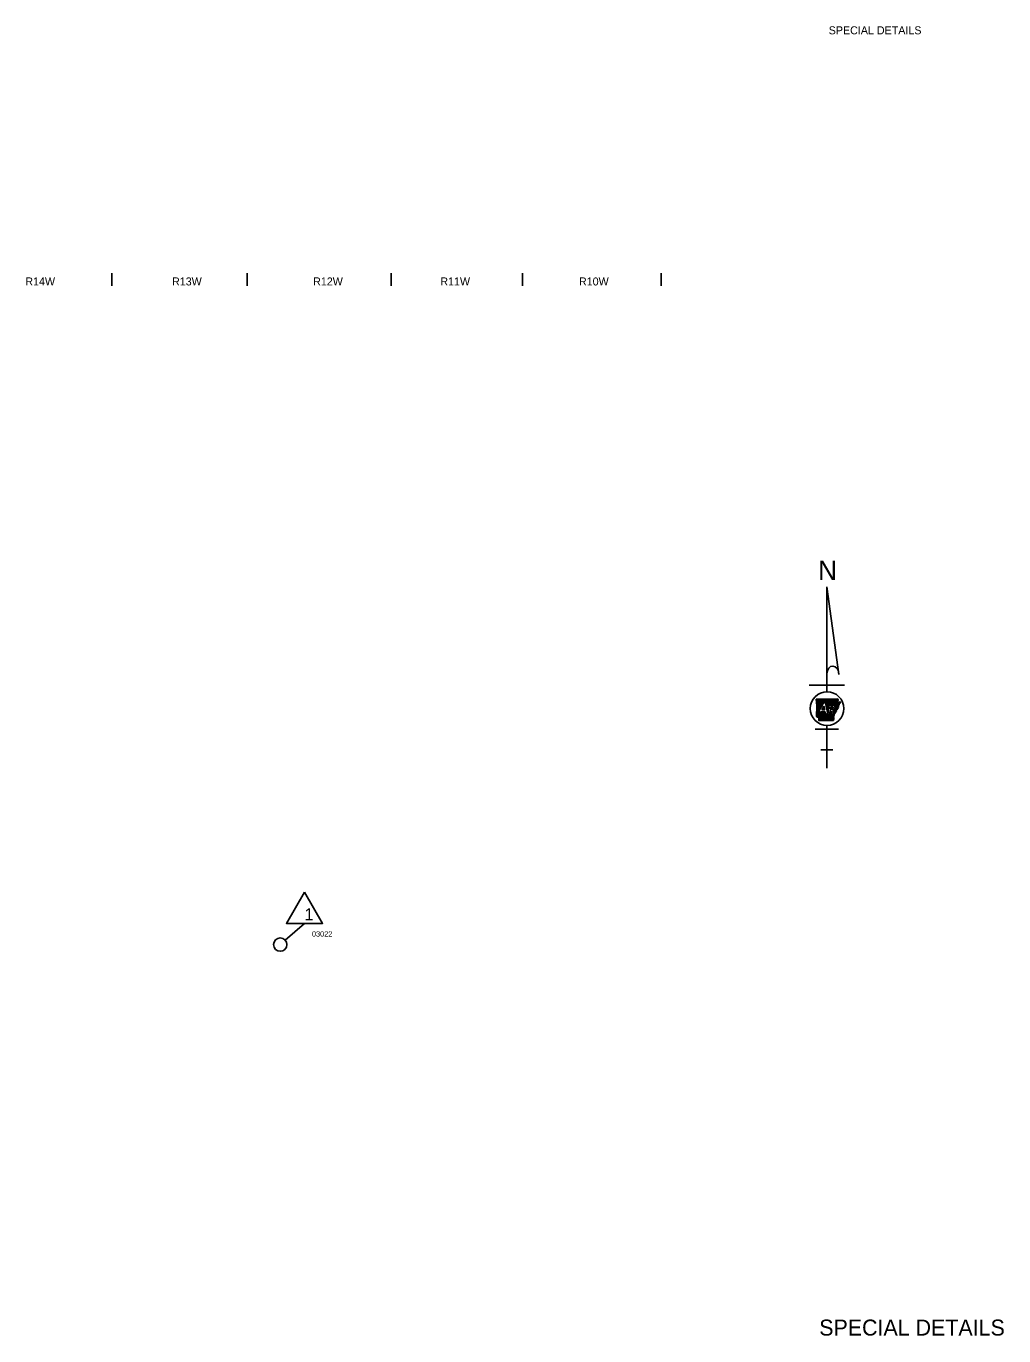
# Model space of a CAD drawing. Extents: x -33639 to 34530, y -17264 to 5867.
# Drawn here: x -9431 to -2101, y -4264 to 5557 of the extents above; entities that cross this region are included whole.
import ezdxf

# ---------------------------------------------------------------- set-up
doc = ezdxf.new("R2010")
doc.units = 0
for name, color, linetype in [('2', 7, 'Continuous'), ('Default', 7, 'Continuous'), ('R_Annotation', 7, 'Continuous'), ('R_Border', 7, 'Continuous'), ('R_No Plot', 7, 'Continuous')]:
    doc.layers.add(name, color=color, linetype=linetype)

msp = doc.modelspace()

# ---------------------------------------------------------------- linework, layer by layer
at = {"layer": 'Default'}
for p, q in [((-8789.5, 3704), (-8789.5, 3609)), ((-7774.4, 3704), (-7774.4, 3609)), ((-6694.8, 3704), (-6694.8, 3609)), ((-5709.6, 3704), (-5709.6, 3609)), ((-4669.7, 3704), (-4669.7, 3609))]:
    msp.add_line(p, q, dxfattribs=at)
at = {"layer": 'R_Annotation'}
for p, q in [((-3427.9, 1353.7), (-3337, 696.6)), ((-3427.9, 565.7), (-3427.9, 1353.7)), ((-3559.5, 614.4), (-3296.4, 614.4)), ((-3507.8, 509.3), (-3506.7, 510.4)), ((-3507.4, 506.2), (-3503.2, 510.4)), ((-3507, 503.1), (-3499.7, 510.4)), ((-3506.6, 500), (-3496.2, 510.4)), ((-3506.2, 496.9), (-3492.8, 510.3)), ((-3505.8, 493.8), (-3489.3, 510.3)), ((-3505.4, 490.7), (-3485.8, 510.3)), ((-3505.1, 487.6), (-3482.3, 510.3)), ((-3504.7, 484.5), (-3478.8, 510.3)), ((-3504.3, 481.4), (-3475.3, 510.3)), ((-3503.9, 478.3), (-3471.9, 510.3)), ((-3503.5, 475.2), (-3468.4, 510.3)), ((-3503.1, 472.1), (-3464.9, 510.3)), ((-3502.7, 469), (-3461.4, 510.3)), ((-3502.6, 434.3), (-3426.5, 510.4)), ((-3502.5, 437.9), (-3430, 510.4)), ((-3502.4, 441.5), (-3433.5, 510.4)), ((-3502.4, 465.9), (-3457.9, 510.3)), ((-3502.3, 445.1), (-3437, 510.4)), ((-3502.2, 448.7), (-3440.5, 510.4)), ((-3502, 452.3), (-3444, 510.4)), ((-3502, 462.8), (-3454.5, 510.3)), ((-3501.9, 455.9), (-3447.5, 510.4)), ((-3501.8, 459.5), (-3451, 510.3)), ((-3450.9, 482.5), (-3423, 510.4)), ((-3447.4, 482.5), (-3419.5, 510.4)), ((-3443.9, 482.5), (-3416, 510.4)), ((-3440.5, 482.5), (-3412.5, 510.5)), ((-3438.3, 481.2), (-3409, 510.6)), ((-3437.7, 478.4), (-3405.4, 510.6)), ((-3437.1, 475.5), (-3401.9, 510.7)), ((-3436.5, 472.6), (-3398.3, 510.7)), ((-3435.8, 469.7), (-3394.8, 510.8)), ((-3435.2, 466.9), (-3391.3, 510.8)), ((-3434.6, 464), (-3387.7, 510.9)), ((-3434, 461.1), (-3384.2, 510.9)), ((-3433.4, 458.3), (-3380.7, 511)), ((-3432.8, 455.4), (-3377.1, 511)), ((-3432.2, 452.5), (-3373.6, 511.1)), ((-3431.5, 449.7), (-3370, 511.2)), ((-3430.9, 446.8), (-3366.5, 511.2)), ((-3430.3, 443.9), (-3362.9, 511.3)), ((-3406.1, 464.6), (-3359.4, 511.4)), ((-3402.6, 464.6), (-3355.8, 511.5)), ((-3399.2, 464.6), (-3352.2, 511.6)), ((-3395.7, 464.6), (-3348.7, 511.6)), ((-3392.2, 464.6), (-3345.1, 511.7)), ((-3388.7, 464.6), (-3344.3, 509)), ((-3385.2, 464.6), (-3342.6, 507.2)), ((-3381.7, 464.6), (-3342.2, 504.2)), ((-3378.3, 464.6), (-3350.1, 492.7)), ((-3504.4, 380.3), (-3488, 396.7)), ((-3504.3, 383.9), (-3491.4, 396.7)), ((-3504.2, 387.5), (-3494.9, 396.7)), ((-3504.1, 391.1), (-3498.4, 396.7)), ((-3503.9, 394.7), (-3501.2, 397.4)), ((-3503.8, 398.3), (-3496.7, 405.4)), ((-3503.7, 401.9), (-3492.1, 413.5)), ((-3503.6, 405.5), (-3487.6, 421.5)), ((-3503.5, 409.1), (-3483, 429.5)), ((-3503.3, 412.7), (-3478.5, 437.5)), ((-3503.2, 416.3), (-3473.9, 445.6)), ((-3503.1, 419.9), (-3469.4, 453.6)), ((-3503.1, 378.1), (-3466.5, 414.7)), ((-3503, 423.5), (-3464.8, 461.6)), ((-3502.9, 427.1), (-3460.3, 469.7)), ((-3502.8, 430.7), (-3455.8, 477.7)), ((-3501.6, 396.7), (-3453, 482.5)), ((-3484.9, 396.7), (-3501.6, 396.7)), ((-3501, 376.7), (-3463, 414.7)), ((-3498.5, 375.7), (-3459.5, 414.7)), ((-3494.4, 376.4), (-3456, 414.7)), ((-3490.8, 376.4), (-3452.5, 414.7)), ((-3488.1, 375.7), (-3449.1, 414.7)), ((-3488, 368.9), (-3442.1, 414.7)), ((-3488, 372.3), (-3445.6, 414.7)), ((-3488, 365.4), (-3440.3, 413.1)), ((-3488, 361.9), (-3439.6, 410.2)), ((-3487.9, 358.4), (-3439, 407.4)), ((-3487.9, 355), (-3438.4, 404.5)), ((-3487.9, 351.5), (-3437.8, 401.6)), ((-3474.7, 414.7), (-3484.9, 396.7)), ((-3484.4, 351.5), (-3437.2, 398.7)), ((-3481, 403.7), (-3469.9, 414.7)), ((-3480.9, 351.5), (-3435.7, 396.7)), ((-3477.4, 351.5), (-3432.2, 396.7)), ((-3476.4, 411.7), (-3473.4, 414.7)), ((-3440.6, 414.7), (-3474.7, 414.7)), ((-3474, 351.5), (-3428.7, 396.7)), ((-3470.5, 351.5), (-3425.3, 396.7)), ((-3467, 351.5), (-3421.8, 396.7)), ((-3465.9, 430.4), (-3450, 458.5)), ((-3465.9, 430.4), (-3444, 430.4)), ((-3465.7, 430.4), (-3447.8, 448.3)), ((-3463.5, 351.5), (-3418.3, 396.7)), ((-3462.2, 430.4), (-3447.2, 445.4)), ((-3461.5, 438.1), (-3448.4, 451.2)), ((-3460.1, 351.5), (-3414.8, 396.7)), ((-3458.7, 430.4), (-3446.6, 442.6)), ((-3457, 446.1), (-3449, 454)), ((-3456.6, 351.5), (-3411.3, 396.7)), ((-3455.2, 430.4), (-3445.9, 439.7)), ((-3453.1, 351.5), (-3393.2, 411.4)), ((-3453, 482.5), (-3438.6, 482.5)), ((-3452.4, 454.1), (-3449.6, 456.9)), ((-3451.8, 430.4), (-3445.3, 436.8)), ((-3449.6, 351.5), (-3392.3, 408.8)), ((-3448.3, 430.4), (-3444.7, 434)), ((-3446.2, 351.5), (-3391.3, 406.3)), ((-3444.8, 430.4), (-3444.1, 431.1)), ((-3442.7, 351.5), (-3390.4, 403.7)), ((-3439.2, 351.5), (-3389.4, 401.2)), ((-3408.5, 396.7), (-3436.8, 396.7)), ((-3435.7, 351.4), (-3388.5, 398.7)), ((-3432.2, 351.4), (-3386.9, 396.7)), ((-3429.7, 441.1), (-3409.9, 460.8)), ((-3429.1, 438.2), (-3410.7, 456.6)), ((-3428.8, 351.4), (-3383.5, 396.7)), ((-3428.5, 435.3), (-3411.4, 452.4)), ((-3427.9, 432.5), (-3412.1, 448.2)), ((-3427.2, 429.6), (-3412.9, 443.9)), ((-3426.6, 426.7), (-3413.6, 439.7)), ((-3426, 423.8), (-3414.3, 435.5)), ((-3425.4, 421), (-3415.1, 431.3)), ((-3425.3, 351.4), (-3380, 396.7)), ((-3424.8, 418.1), (-3415.8, 427.1)), ((-3424.2, 415.2), (-3416.5, 422.9)), ((-3423.6, 412.4), (-3417.3, 418.6)), ((-3422.9, 409.5), (-3418, 414.4)), ((-3422.3, 406.6), (-3418.8, 410.2)), ((-3421.8, 351.4), (-3376.5, 396.7)), ((-3421.7, 403.8), (-3419.5, 406)), ((-3421.1, 400.9), (-3420.2, 401.8)), ((-3418.3, 351.4), (-3375.3, 394.4)), ((-3409.3, 464.6), (-3375.5, 464.6)), ((-3407.9, 400.2), (-3394.1, 413.9)), ((-3407.1, 404.4), (-3395.1, 416.5)), ((-3406.4, 408.6), (-3396, 419)), ((-3405.7, 412.8), (-3397, 421.6)), ((-3404.9, 417.1), (-3398, 424)), ((-3404.2, 421.3), (-3401.5, 424)), ((-3397.9, 424), (-3403.7, 424)), ((-3401.9, 434.2), (-3383.6, 452.5)), ((-3401.9, 434.2), (-3387.5, 434.2)), ((-3401.2, 438.4), (-3387.1, 452.5)), ((-3400.5, 442.6), (-3390.6, 452.5)), ((-3399.7, 446.8), (-3394.1, 452.5)), ((-3399, 451.1), (-3397.5, 452.5)), ((-3398.8, 452.5), (-3382.9, 452.5)), ((-3398.4, 434.2), (-3381.7, 451)), ((-3387.8, 396.7), (-3397.9, 424)), ((-3395, 434.2), (-3380.5, 448.7)), ((-3391.5, 434.2), (-3379.8, 445.8)), ((-3388, 434.2), (-3380.1, 442.1)), ((-3373, 396.7), (-3387.8, 396.7)), ((-3383.6, 425.5), (-3373, 396.7)), ((-3383.3, 424.7), (-3382.3, 425.8)), ((-3382.4, 422.2), (-3375.8, 428.8)), ((-3381.4, 419.7), (-3342.8, 458.3)), ((-3380.5, 417.1), (-3342.2, 455.4)), ((-3379.6, 414.6), (-3341.5, 452.6)), ((-3378.6, 412), (-3340.9, 449.8)), ((-3377.7, 409.5), (-3356.8, 430.4)), ((-3376.7, 406.9), (-3357.2, 426.5)), ((-3375.8, 404.4), (-3357.6, 422.6)), ((-3375.1, 464.3), (-3350.8, 488.6)), ((-3374.9, 401.9), (-3364.2, 412.5)), ((-3373.9, 399.3), (-3365.7, 407.6)), ((-3373.2, 462.7), (-3347.2, 488.8)), ((-3371.5, 461), (-3343.5, 489)), ((-3370.1, 434.5), (-3343.5, 461.1)), ((-3370, 459), (-3339.8, 489.1)), ((-3368.7, 456.8), (-3336.1, 489.3)), ((-3367.6, 454.4), (-3332.5, 489.5)), ((-3367.1, 441), (-3335.4, 472.6)), ((-3366.8, 451.7), (-3329.2, 489.3)), ((-3366.4, 448.7), (-3327.5, 487.5)), ((-3366.3, 445.2), (-3335.9, 475.7)), ((-3352.8, 434.4), (-3347.9, 439.3)), ((-3339.4, 465.2), (-3335, 469.5)), ((-3329.1, 482.5), (-3325.9, 485.6)), ((-3427.9, -6.1), (-3427.9, 313.7)), ((-3414.9, 351.4), (-3375.2, 391.1)), ((-3411.4, 351.4), (-3375, 387.8)), ((-3407.9, 351.4), (-3374.9, 384.4)), ((-3404.4, 351.4), (-3380.6, 375.2)), ((-3400.9, 351.4), (-3379.5, 372.8)), ((-3397.5, 351.4), (-3378.4, 370.4)), ((-3394, 351.4), (-3377.4, 368)), ((-3390.5, 351.4), (-3376.3, 365.6)), ((-3387, 351.4), (-3375.4, 363)), ((-3383.6, 351.4), (-3377, 358)), ((-3380.1, 351.4), (-3378.5, 352.9)), ((-3515.7, 286.5), (-3340.2, 286.5)), ((-3471.8, 130.7), (-3384.1, 130.7)), ((-7344.2, -1171.7), (-7488.2, -1297.6))]:
    msp.add_line(p, q, dxfattribs=at)
for points in [[(-3507.9, 510.3), (-3459.9, 510.3), (-3417.7, 510.4), (-3367.9, 511.2), (-3344.9, 511.7)], [(-3507.9, 510.4), (-3459.8, 510.3), (-3417.7, 510.4), (-3367.9, 511.2), (-3344.9, 511.7)], [(-3504.4, 380.4), (-3501.7, 461), (-3507.9, 510.4)], [(-3502.6, 435.7), (-3501.8, 461), (-3507.9, 510.3)], [(-3504.4, 380.3), (-3502.6, 435.7)], [(-3450, 458.5), (-3444, 430.4)], [(-3436.8, 396.7), (-3440.6, 414.7)], [(-3438.6, 482.5), (-3420.7, 399), (-3409.3, 464.6)], [(-3403.7, 424), (-3408.5, 396.7)], [(-3401.9, 434.2), (-3398.8, 452.5)], [(-3329.8, 489.6), (-3325.6, 485.3), (-3336, 476.8), (-3334.9, 468.2), (-3343.8, 462.3), (-3340.7, 449.1), (-3347.6, 442.8), (-3348.2, 436), (-3356.5, 433), (-3357.8, 420.2), (-3363.8, 413.8), (-3366.7, 404.1), (-3375.4, 396.2), (-3374.8, 382.1), (-3380.7, 375.4), (-3375.3, 363.4), (-3379, 351.4)], [(-3352, 488.5), (-3329.5, 489.7)], [(-3352, 488.5), (-3329.5, 489.7)], [(-3379, 351.3), (-3487.9, 351.5), (-3488, 375.6)], [(-3379, 351.4), (-3487.9, 351.5), (-3488, 375.6)]]:
    msp.add_lwpolyline(points, dxfattribs=at)
msp.add_lwpolyline([(-7344.2, -937.9), (-7209.2, -1171.7), (-7479.2, -1171.7)], close=True, dxfattribs=at)
msp.add_circle((-7525.9, -1330.5), 50, dxfattribs=at)
for centre, major_axis, ratio, start_param, end_param in [((-3382.5, 695.2), (-1.9, 63.2), 0.719778, 4.712385, 7.768526), ((-3390.9, 444.8), (-11.1, 0), 0.999987, 1.887169, 3.90762), ((-3388.1, 446.8), (-21.8, 0), 0.999987, 1.777838, 4.099264)]:
    msp.add_ellipse(centre, major_axis=major_axis, ratio=ratio, start_param=start_param, end_param=end_param, dxfattribs=at)
msp.add_ellipse((-3425.9, 439.7), major_axis=(126, 0), ratio=0.999976, dxfattribs=at)
for points in [[(-3344.9, 511.7), (-3344.7, 510.4), (-3344.3, 509.7), (-3344.3, 508.5), (-3343.7, 507.9), (-3342.9, 507.4), (-3342.1, 506.6), (-3341.9, 505.6), (-3342.2, 504.5), (-3342.2, 503.3), (-3342.3, 502.3), (-3342.5, 501.4), (-3343.2, 500.7), (-3343.9, 500.1), (-3344.5, 499.5), (-3345, 498.9), (-3345.8, 498.2), (-3346.5, 497.4), (-3347.2, 496.8), (-3347.8, 495.9), (-3348.1, 495), (-3348.8, 494.3), (-3349.3, 493.7), (-3350, 492.9), (-3350.4, 492.2), (-3351, 491.2), (-3351.2, 490.3), (-3351.6, 489.6), (-3351.7, 489.5)], [(-3344.9, 511.7), (-3344.7, 510.4), (-3344.3, 509.7), (-3344.3, 508.5), (-3343.7, 508), (-3342.9, 507.4), (-3342.1, 506.6), (-3341.9, 505.5), (-3342.2, 504.5), (-3342.2, 503.3), (-3342.4, 502.3), (-3342.5, 501.4), (-3343.2, 500.7), (-3343.9, 500.1), (-3344.6, 499.5), (-3345, 498.9), (-3345.8, 498.1), (-3346.5, 497.4), (-3347.2, 496.7), (-3347.8, 495.9), (-3348.1, 495), (-3348.8, 494.3), (-3349.3, 493.7), (-3350, 492.9), (-3350.4, 492.1), (-3351.1, 491.2), (-3351.2, 490.3), (-3351.7, 489.6), (-3351.7, 489.5)], [(-3370.5, 403.5), (-3370.6, 403.4), (-3371.1, 402.8), (-3370.8, 401.7), (-3369.6, 401.3), (-3369.1, 400.3), (-3369.1, 399.4), (-3369.4, 398.2), (-3370, 397.6), (-3371, 397.4), (-3371.8, 397.2), (-3371.9, 395.9), (-3372.3, 395.2), (-3372.9, 395), (-3373.8, 395.4), (-3374.4, 395.7), (-3375, 395.9), (-3375.8, 396.4), (-3376.5, 396.3), (-3376.3, 395), (-3376.2, 395), (-3375.5, 394), (-3374.8, 393.2), (-3374.5, 392.3)], [(-3370.5, 403.5), (-3370.6, 403.4), (-3371.1, 402.8), (-3370.8, 401.7), (-3369.6, 401.3), (-3369.1, 400.3), (-3369.1, 399.4), (-3369.4, 398.2), (-3370, 397.6), (-3371, 397.4), (-3371.8, 397.2), (-3371.9, 395.9), (-3372.3, 395.2), (-3372.9, 395), (-3373.8, 395.4), (-3374.4, 395.7), (-3375, 395.9), (-3375.8, 396.4), (-3376.5, 396.3), (-3376.3, 395), (-3376.2, 395), (-3375.5, 394), (-3374.8, 393.2), (-3374.5, 392.3)], [(-3354, 431.6), (-3355, 430.8), (-3355.5, 430), (-3358.2, 430.2), (-3358.1, 429.3), (-3359, 428.8), (-3359.9, 428.2), (-3359.4, 427.5), (-3358.5, 426.8), (-3357.6, 426.3), (-3357, 425.8), (-3356.9, 424.6), (-3356.7, 423.8), (-3356.4, 422.8), (-3356.3, 422), (-3356.9, 421.2), (-3357.5, 421), (-3358.1, 421.2), (-3358.9, 421.2), (-3359.5, 420.7), (-3360, 419.8), (-3360.4, 419), (-3360.7, 418.3), (-3361.1, 417.5), (-3361.7, 416.6), (-3362.5, 416.5), (-3363.5, 416.2), (-3364, 415.6), (-3363.9, 414.5), (-3363.4, 413.7), (-3363, 412.8), (-3362.7, 412), (-3362.8, 411), (-3363.3, 410.2), (-3363.8, 409.8), (-3364, 408.8), (-3364.4, 408.1), (-3364.8, 407.9), (-3365.5, 408), (-3366.3, 408.1), (-3366.9, 408), (-3367.5, 407.7), (-3368.2, 407.9), (-3368.8, 408.6), (-3369.4, 409.2), (-3370, 409.4), (-3370.6, 409.1), (-3370.7, 408.1), (-3370.4, 407.1), (-3370.1, 405.7), (-3370.4, 404.9), (-3370.5, 403.5)], [(-3341.1, 461.1), (-3341, 460.2), (-3341.5, 459.3), (-3341.7, 458.4), (-3341.6, 457.4), (-3342.5, 456.9), (-3343.4, 456.3), (-3342.9, 455.6), (-3342, 455), (-3341.1, 454.5), (-3340.6, 454), (-3340.4, 452.8), (-3340.2, 452), (-3339.9, 450.9), (-3339.8, 450.2), (-3340.4, 449.3), (-3341, 449.1), (-3341.7, 449.3), (-3342.4, 449.3), (-3343, 448.8), (-3343.5, 447.9), (-3343.9, 447.1), (-3344.3, 446.4), (-3344.6, 445.6), (-3345.2, 444.7), (-3346, 444.6), (-3347, 444.3), (-3347.6, 443.7), (-3347.5, 442.6), (-3346.9, 441.8), (-3346.5, 440.9), (-3346.2, 440.1), (-3346.4, 439.1), (-3346.8, 438.4), (-3347.3, 437.9), (-3347.6, 437), (-3347.9, 436.2), (-3348.3, 436), (-3349, 436.1), (-3349.8, 436.2), (-3350.4, 436.2), (-3351, 435.8), (-3351.7, 436), (-3352.3, 436.8), (-3352.9, 437.3), (-3353.5, 437.5), (-3354.1, 437.2), (-3354.2, 436.2), (-3353.9, 435.2), (-3353.6, 433.8), (-3353.9, 433), (-3354, 431.6)], [(-3329.8, 489.7), (-3329.5, 489.7), (-3328.5, 488.6), (-3328, 487.7), (-3327.3, 487.2), (-3326.6, 487), (-3326, 486.3), (-3325.7, 485.5), (-3325.9, 484.9), (-3326.7, 484.8), (-3327.6, 484.7), (-3328.5, 484.7), (-3329.2, 484.1), (-3328.6, 483.3), (-3327.7, 482.5), (-3327.5, 481.7), (-3327.9, 481), (-3328.9, 480.6), (-3329.8, 480.2), (-3330.6, 479.5), (-3331, 478.8), (-3332, 478.5), (-3332.9, 478.2), (-3333.7, 478.1), (-3334.7, 478), (-3335.6, 477.5), (-3336, 476.7), (-3335.9, 475.7), (-3335.9, 474.5), (-3334.9, 474.1), (-3334.1, 474.1), (-3333.2, 473.6), (-3333.3, 473), (-3333.9, 472.1), (-3334.7, 471.5), (-3335.4, 471.2), (-3336.1, 470.5), (-3335.9, 469.9), (-3335.3, 469.5), (-3334.8, 468.8), (-3334.9, 468.2), (-3335.6, 467.8), (-3336.4, 467.9), (-3336.9, 468.7), (-3337.6, 468.9), (-3338.1, 469.2), (-3338.8, 468.8), (-3338.8, 467.9), (-3339, 467), (-3338.8, 466.3), (-3338.6, 465.4), (-3338.6, 464.7), (-3338.8, 463.6), (-3339.3, 462.6), (-3339.9, 462.3), (-3340.2, 463.4), (-3340.3, 464.3), (-3340.6, 464.9), (-3341.1, 464.9), (-3341.7, 464.5), (-3342.4, 463.8), (-3343.3, 463), (-3343.8, 462.3), (-3343.5, 461.4), (-3342.9, 461.1), (-3342.3, 461.3), (-3342.1, 461.9), (-3341.6, 462), (-3341.1, 461.1)], [(-3488, 375.6), (-3487.9, 375.5), (-3488.4, 375.9), (-3489.2, 376.3), (-3490.1, 376.3), (-3491.2, 376.5), (-3492.1, 376.6), (-3493, 377.2), (-3494.1, 376.6), (-3495.2, 376.1), (-3495.8, 376.6), (-3496.7, 376.3), (-3497.3, 376.4), (-3498.3, 375.7), (-3499.3, 376), (-3500, 375.8), (-3500.9, 375.8), (-3501.1, 376.8), (-3502, 377), (-3502.7, 377.4), (-3503.2, 378.4), (-3503.6, 379.2), (-3504.4, 380.4)], [(-3488, 375.6), (-3487.9, 375.5), (-3488.4, 375.9), (-3489.2, 376.3), (-3490.1, 376.3), (-3491.2, 376.5), (-3492.1, 376.6), (-3493, 377.2), (-3494, 376.6), (-3495.2, 376.1), (-3495.8, 376.6), (-3496.7, 376.2), (-3497.3, 376.4), (-3498.3, 375.7), (-3499.3, 376), (-3500, 375.8), (-3500.9, 375.8), (-3501.1, 376.8), (-3502, 377), (-3502.7, 377.4), (-3503.2, 378.4), (-3503.6, 379.2), (-3504.4, 380.3)], [(-3374.5, 392.3), (-3374.8, 391.6), (-3375.1, 390.4), (-3375, 389.4), (-3374.6, 388.6), (-3373.9, 388.1), (-3373.1, 387.4), (-3373.1, 386.4), (-3373.6, 386), (-3374.6, 386.2), (-3375.4, 386.6), (-3376.1, 386.4), (-3377, 386), (-3377.7, 385.8), (-3377.7, 384.4), (-3376.8, 383.4), (-3376, 383.4), (-3375, 383.3), (-3374.7, 382.2), (-3375.3, 381.3), (-3376.1, 380.9), (-3377.3, 381.4), (-3378.1, 382), (-3378.9, 382.5), (-3379.9, 382.8), (-3380.5, 382.7), (-3380.7, 381.4), (-3380.2, 380.3), (-3379.5, 379.5), (-3378.8, 378.5), (-3378.9, 377.8), (-3379.4, 377.6), (-3380.4, 377.3), (-3380.9, 377.1), (-3381.1, 376.8), (-3380.8, 375.8), (-3380.5, 374.7), (-3380.5, 373.9), (-3380.8, 373.1), (-3381.3, 371.9), (-3381.3, 371.2), (-3380.9, 370.8), (-3380.5, 370.9), (-3379.9, 371.3), (-3379.5, 371.8), (-3379.2, 372.4), (-3378.6, 372.9), (-3377.8, 372.5), (-3377.6, 371.5), (-3378, 370.7), (-3378.7, 370.4), (-3379.4, 370.1), (-3380, 369.4), (-3379.9, 368.6), (-3379.4, 368.2), (-3378.3, 368.4), (-3377.6, 368.8), (-3377.1, 369.2), (-3376.6, 369.7), (-3376.4, 370.2), (-3376, 370.7), (-3375.3, 370.9), (-3375, 370.4), (-3375.1, 369.4), (-3375.5, 368.5), (-3376.1, 367.7), (-3376.7, 367.1), (-3377.5, 365.9), (-3377.3, 364.8), (-3377, 363.8), (-3376.6, 363.1), (-3375.9, 363.3), (-3375.1, 363.4), (-3374.6, 363), (-3374.7, 362.1), (-3375.3, 361.3), (-3375.8, 360.6), (-3376.1, 359.5), (-3376, 358.7), (-3376, 358.1), (-3376.3, 357.3), (-3376.7, 356.9), (-3377.8, 356.9), (-3378.9, 357), (-3379.6, 356.7), (-3379.4, 355.7), (-3378.8, 354.9), (-3378.3, 354.6), (-3377.6, 353.7), (-3377.3, 353), (-3377.4, 352.5), (-3377.8, 351.9), (-3379, 351.3)], [(-3374.5, 392.3), (-3374.8, 391.6), (-3375.1, 390.4), (-3375, 389.4), (-3374.6, 388.6), (-3373.9, 388.1), (-3373.1, 387.4), (-3373.1, 386.4), (-3373.6, 386), (-3374.6, 386.2), (-3375.4, 386.6), (-3376.1, 386.4), (-3377, 386), (-3377.7, 385.8), (-3377.7, 384.4), (-3376.8, 383.4), (-3376, 383.4), (-3375, 383.3), (-3374.7, 382.2), (-3375.3, 381.3), (-3376.1, 380.9), (-3377.3, 381.4), (-3378.1, 382), (-3378.9, 382.5), (-3379.9, 382.8), (-3380.5, 382.7), (-3380.7, 381.4), (-3380.2, 380.3), (-3379.5, 379.5), (-3378.8, 378.5), (-3378.9, 377.8), (-3379.4, 377.6), (-3380.4, 377.3), (-3380.9, 377.1), (-3381.1, 376.8), (-3380.8, 375.8), (-3380.5, 374.7), (-3380.5, 373.9), (-3380.8, 373.1), (-3381.3, 371.9), (-3381.3, 371.2), (-3380.9, 370.8), (-3380.5, 370.9), (-3379.9, 371.3), (-3379.5, 371.8), (-3379.2, 372.4), (-3378.6, 372.9), (-3377.8, 372.5), (-3377.6, 371.5), (-3378, 370.7), (-3378.7, 370.4), (-3379.4, 370.1), (-3380, 369.4), (-3379.9, 368.6), (-3379.4, 368.2), (-3378.3, 368.4), (-3377.6, 368.8), (-3377.1, 369.2), (-3376.6, 369.7), (-3376.4, 370.2), (-3376, 370.7), (-3375.3, 370.9), (-3375, 370.4), (-3375.1, 369.4), (-3375.5, 368.5), (-3376.1, 367.7), (-3376.7, 367.1), (-3377.5, 365.9), (-3377.3, 364.8), (-3377, 363.8), (-3376.6, 363.1), (-3375.9, 363.3), (-3375.1, 363.4), (-3374.6, 363), (-3374.7, 362.1), (-3375.3, 361.3), (-3375.8, 360.6), (-3376.1, 359.5), (-3376, 358.7), (-3376, 358.1), (-3376.3, 357.3), (-3376.7, 356.9), (-3377.8, 356.9), (-3378.9, 357), (-3379.6, 356.7), (-3379.4, 355.7), (-3378.8, 354.9), (-3378.3, 354.6), (-3377.6, 353.7), (-3377.3, 353), (-3377.4, 352.5), (-3377.8, 351.9), (-3379, 351.3)]]:
    msp.add_spline(points, degree=3, dxfattribs=at)

# ---------------------------------------------------------------- texts
at = {"layer": '2'}
for s, p in [('R14W', (-9437.5, 3613.1)), ('R13W', (-8337.5, 3613.1)), ('R12W', (-7279.7, 3613.1)), ('R11W', (-6325.8, 3613.1)), ('R10W', (-5286.2, 3613.1))]:
    msp.add_text(s, height=60, dxfattribs=at).set_placement(p)
at = {"layer": 'R_Annotation'}
for s, height, p in [('N', 146.7, (-3493.3, 1403.2)), ('STS 10-03-17', 3.644, (-3437.9, 314.7)), ('1', 90, (-7344, -1148.4)), ('SPECIAL DETAILS', 120, (-3484.9, -4262.4))]:
    msp.add_text(s, height=height, dxfattribs=at).set_placement(p)
at = {"layer": 'R_Border'}
msp.add_text('SPECIAL DETAILS', height=60, dxfattribs=at).set_placement((-3413.9, 5496.5))
at = {"layer": 'R_No Plot'}
msp.add_text('03022', height=40, dxfattribs=at).set_placement((-7288.6, -1270))

doc.saveas('drawing.dxf')
